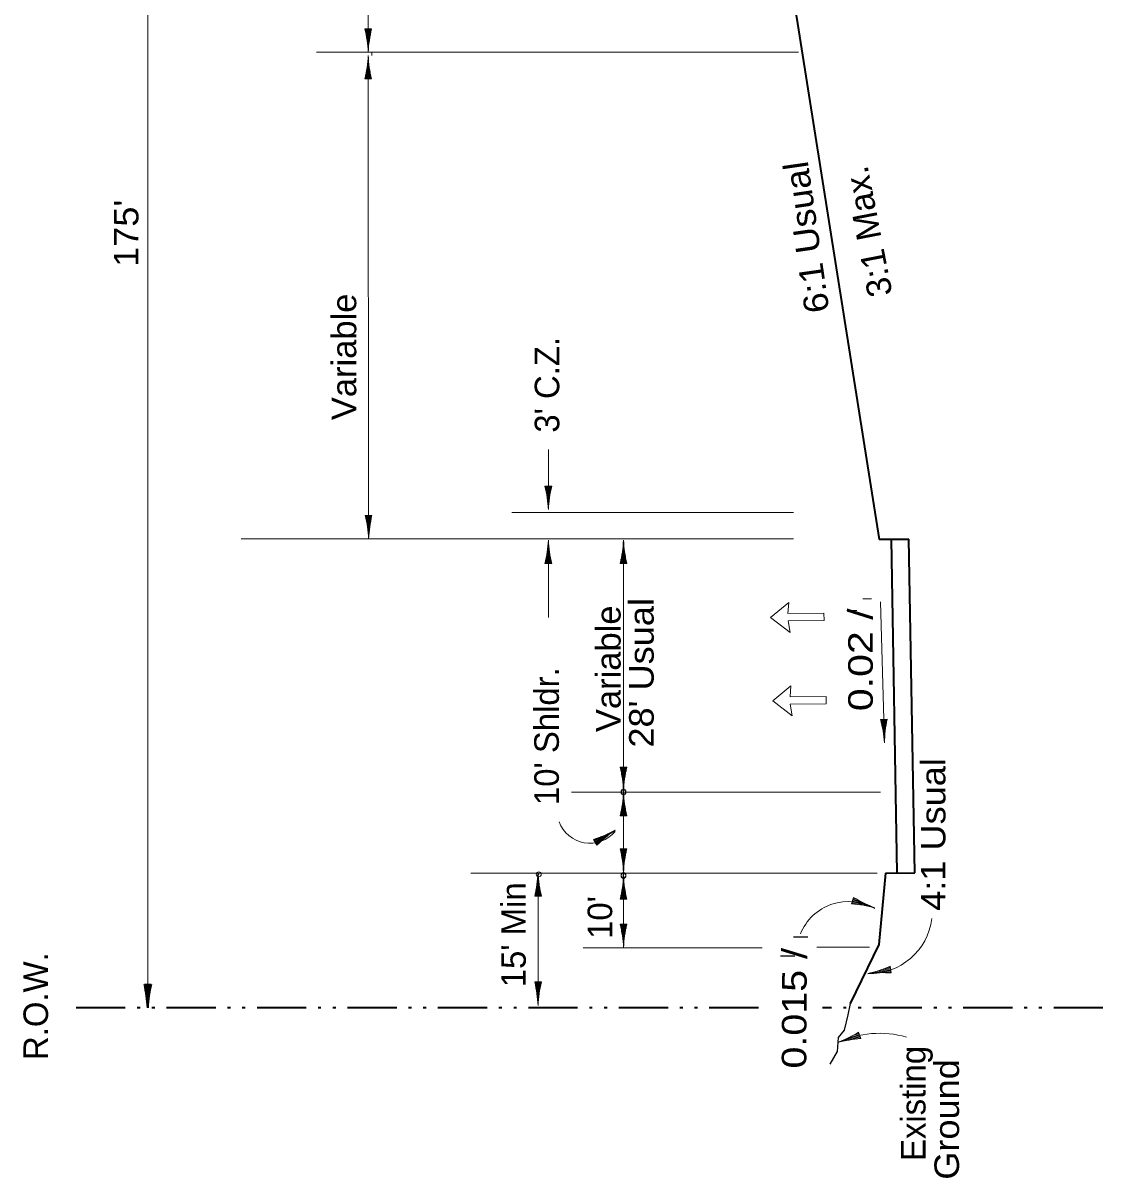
# Model space of a CAD drawing. Extents: x 2363427 to 2368559, y 6957299 to 6980140.
# Drawn here: x 2363636 to 2364251, y 6962683 to 6963341 of the extents above; entities that cross this region are included whole.
import ezdxf
from ezdxf.enums import TextEntityAlignment as Align

# ---------------------------------------------------------------- set-up
doc = ezdxf.new("R2010")
doc.units = 0
doc.header["$LTSCALE"] = 5.6
doc.header["$PDMODE"] = 32
doc.header["$PDSIZE"] = 2.8
doc.linetypes.add('DASH_DOUBLE_DOT', pattern=[9.2, 5, -1.2, 0.3, -1.2, 0.3, -1.2])
doc.linetypes.add('MEDIUM_DASHED', pattern=[4.5, 3, -1.5])
for name, color, linetype, lineweight in [('1', 7, 'Continuous', 13), ('3', 7, 'Continuous', 35), ('4', 7, 'Continuous', 13), ('40', 7, 'Continuous', 35), ('48', 7, 'Continuous', 25), ('6', 7, 'Continuous', 13), ('8', 7, 'Continuous', 13)]:
    doc.layers.add(name, color=color, linetype=linetype, lineweight=lineweight)

msp = doc.modelspace()

# ---------------------------------------------------------------- linework, layer by layer
at = {"layer": '1'}
msp.add_line((2363707.002, 6962780.153), (2363707.002, 6963655.227), dxfattribs=at)
at = {"layer": '1', "linetype": 'MEDIUM_DASHED', "lineweight": 25}
msp.add_lwpolyline([(2364107.062, 6962782.646), (2364105.71, 6962776.144), (2364103.682, 6962767.474), (2364100.302, 6962763.14), (2364099.626, 6962755.192), (2364095.57, 6962747.968)], dxfattribs=at)
at = {"layer": '3'}
for p, q in [((2364063.96, 6963424.356), (2364123.57, 6963047.006)), ((2364140.593, 6963047.007), (2364123.57, 6963047.006)), ((2364133.913, 6962856.972), (2364130.592, 6963047.007)), ((2364143.911, 6962857.081), (2364140.591, 6963047.094)), ((2364127.321, 6962856.943), (2364123.465, 6962816.178)), ((2364127.321, 6962856.943), (2364143.913, 6962857.015)), ((2364123.465, 6962816.179), (2364107.063, 6962782.648))]:
    msp.add_line(p, q, dxfattribs=at)
at = {"layer": '3', "lineweight": 13}
for p, q in [((2364077.609, 6963324.652), (2363803.11, 6963324.652)), ((2364074.775, 6963062.399), (2363914.323, 6963062.399)), ((2364074.775, 6963047.399), (2363760.2, 6963047.399))]:
    msp.add_line(p, q, dxfattribs=at)
at = {"layer": '3', "linetype": 'DASH_DOUBLE_DOT'}
for p, q in [((2364054.887, 6962780.227), (2363665.024, 6962780.227)), ((2364251.073, 6962780.227), (2364091.319, 6962780.227))]:
    msp.add_line(p, q, dxfattribs=at)
at = {"layer": '4'}
for p, q in [((2363977.999, 6963046.638), (2363977.999, 6962814.405)), ((2363978.063, 6963033.326), (2363978.063, 6963045.89)), ((2363978.063, 6963033.326), (2363978.063, 6963045.89)), ((2363977.563, 6963033.326), (2363977.563, 6963041.936)), ((2363977.563, 6963033.326), (2363977.563, 6963041.936)), ((2363978.563, 6963033.326), (2363978.563, 6963040.676)), ((2363978.563, 6963033.326), (2363978.563, 6963040.676)), ((2363979.913, 6963033.326), (2363976.083, 6963033.326)), ((2363979.913, 6963033.326), (2363976.083, 6963033.326)), ((2363976.563, 6963033.326), (2363976.563, 6963035.708)), ((2363976.563, 6963033.326), (2363976.563, 6963035.708)), ((2363977.063, 6963033.326), (2363977.063, 6963038.188)), ((2363977.063, 6963033.326), (2363977.063, 6963038.188)), ((2363979.063, 6963033.326), (2363979.063, 6963037.603)), ((2363979.063, 6963033.326), (2363979.063, 6963037.603)), ((2363979.563, 6963033.326), (2363979.563, 6963034.912)), ((2363979.563, 6963033.326), (2363979.563, 6963034.912)), ((2364124.385, 6963011.452), (2364126.661, 6962931.198)), ((2364128.197, 6962944.559), (2364124.369, 6962944.45)), ((2364124.849, 6962944.464), (2364124.917, 6962942.084)), ((2364125.349, 6962944.478), (2364125.487, 6962939.618)), ((2364125.849, 6962944.492), (2364126.093, 6962935.886)), ((2364126.348, 6962944.506), (2364126.705, 6962931.948)), ((2364126.848, 6962944.52), (2364127.057, 6962937.174)), ((2364127.348, 6962944.535), (2364127.469, 6962940.26)), ((2364127.847, 6962944.549), (2364127.893, 6962942.964)), ((2363976.083, 6962917.24), (2363979.913, 6962917.24)), ((2363976.083, 6962917.24), (2363979.913, 6962917.24)), ((2363976.433, 6962917.24), (2363976.433, 6962915.656)), ((2363976.433, 6962917.24), (2363976.433, 6962915.656)), ((2363976.933, 6962917.24), (2363976.933, 6962912.964)), ((2363976.933, 6962917.24), (2363976.933, 6962912.964)), ((2363977.433, 6962917.24), (2363977.433, 6962909.89)), ((2363977.433, 6962917.24), (2363977.433, 6962909.89)), ((2363977.933, 6962917.24), (2363977.933, 6962904.676)), ((2363977.933, 6962917.24), (2363977.933, 6962904.676)), ((2363978.433, 6962917.24), (2363978.433, 6962908.631)), ((2363978.433, 6962917.24), (2363978.433, 6962908.631)), ((2363978.933, 6962917.24), (2363978.933, 6962912.378)), ((2363978.933, 6962917.24), (2363978.933, 6962912.378)), ((2363979.433, 6962917.24), (2363979.433, 6962914.859)), ((2363979.433, 6962917.24), (2363979.433, 6962914.859)), ((2364124.346, 6962902.943), (2363948.478, 6962902.943)), ((2363978.063, 6962889.591), (2363978.063, 6962902.155)), ((2363978.063, 6962889.591), (2363978.063, 6962902.155)), ((2363977.063, 6962889.591), (2363977.063, 6962894.453)), ((2363977.063, 6962889.591), (2363977.063, 6962894.453)), ((2363977.563, 6962889.591), (2363977.563, 6962898.201)), ((2363977.563, 6962889.591), (2363977.563, 6962898.201)), ((2363978.563, 6962889.591), (2363978.563, 6962896.941)), ((2363978.563, 6962889.591), (2363978.563, 6962896.941)), ((2363979.913, 6962889.591), (2363976.083, 6962889.591)), ((2363979.913, 6962889.591), (2363976.083, 6962889.591)), ((2363976.563, 6962889.591), (2363976.563, 6962891.973)), ((2363976.563, 6962889.591), (2363976.563, 6962891.973)), ((2363979.063, 6962889.591), (2363979.063, 6962893.868)), ((2363979.063, 6962889.591), (2363979.063, 6962893.868)), ((2363979.563, 6962889.591), (2363979.563, 6962891.177)), ((2363979.563, 6962889.591), (2363979.563, 6962891.177)), ((2363961.901, 6962874.367), (2363972.641, 6962880.887)), ((2363962.861, 6962872.786), (2363960.873, 6962876.06)), ((2363961.123, 6962875.649), (2363963.158, 6962876.885)), ((2363961.382, 6962875.223), (2363965.538, 6962877.745)), ((2363961.641, 6962874.795), (2363969.001, 6962879.263)), ((2363962.16, 6962873.94), (2363968.443, 6962877.754)), ((2363962.419, 6962873.513), (2363966.075, 6962875.731)), ((2363962.679, 6962873.085), (2363964.034, 6962873.908)), ((2363976.083, 6962870.762), (2363979.913, 6962870.762)), ((2363976.083, 6962870.762), (2363979.913, 6962870.762)), ((2363976.433, 6962870.762), (2363976.433, 6962869.178)), ((2363976.433, 6962870.762), (2363976.433, 6962869.178)), ((2363976.933, 6962870.762), (2363976.933, 6962866.486)), ((2363976.933, 6962870.762), (2363976.933, 6962866.486)), ((2363977.433, 6962870.762), (2363977.433, 6962863.412)), ((2363977.433, 6962870.762), (2363977.433, 6962863.412)), ((2363977.933, 6962870.762), (2363977.933, 6962858.198)), ((2363977.933, 6962870.762), (2363977.933, 6962858.198)), ((2363978.433, 6962870.762), (2363978.433, 6962862.153)), ((2363978.433, 6962870.762), (2363978.433, 6962862.153)), ((2363978.933, 6962870.762), (2363978.933, 6962865.9)), ((2363978.933, 6962870.762), (2363978.933, 6962865.9)), ((2363979.433, 6962870.762), (2363979.433, 6962868.381)), ((2363979.433, 6962870.762), (2363979.433, 6962868.381)), ((2364122.417, 6962856.879), (2363891.088, 6962856.879)), ((2363929.268, 6962843.77), (2363929.268, 6962856.334)), ((2363929.268, 6962843.77), (2363929.268, 6962856.334)), ((2363929.332, 6962857.082), (2363929.332, 6962781.546)), ((2363978.063, 6962841.995), (2363978.063, 6962854.559)), ((2363978.063, 6962841.995), (2363978.063, 6962854.559)), ((2363928.268, 6962843.77), (2363928.268, 6962848.046)), ((2363928.268, 6962843.77), (2363928.268, 6962848.046)), ((2363928.768, 6962843.77), (2363928.768, 6962851.12)), ((2363928.768, 6962843.77), (2363928.768, 6962851.12)), ((2363929.768, 6962843.77), (2363929.768, 6962852.38)), ((2363929.768, 6962843.77), (2363929.768, 6962852.38)), ((2363930.268, 6962843.77), (2363930.268, 6962848.632)), ((2363930.268, 6962843.77), (2363930.268, 6962848.632)), ((2363977.563, 6962841.995), (2363977.563, 6962850.605)), ((2363977.563, 6962841.995), (2363977.563, 6962850.605)), ((2363978.563, 6962841.995), (2363978.563, 6962849.345)), ((2363978.563, 6962841.995), (2363978.563, 6962849.345)), ((2363927.418, 6962843.77), (2363931.248, 6962843.77)), ((2363927.418, 6962843.77), (2363931.248, 6962843.77)), ((2363927.768, 6962843.77), (2363927.768, 6962845.355)), ((2363927.768, 6962843.77), (2363927.768, 6962845.355)), ((2363930.768, 6962843.77), (2363930.768, 6962846.152)), ((2363930.768, 6962843.77), (2363930.768, 6962846.152)), ((2363979.913, 6962841.995), (2363976.083, 6962841.995)), ((2363979.913, 6962841.995), (2363976.083, 6962841.995)), ((2363976.563, 6962841.995), (2363976.563, 6962844.377)), ((2363976.563, 6962841.995), (2363976.563, 6962844.377)), ((2363977.063, 6962841.995), (2363977.063, 6962846.857)), ((2363977.063, 6962841.995), (2363977.063, 6962846.857)), ((2363979.063, 6962841.995), (2363979.063, 6962846.272)), ((2363979.063, 6962841.995), (2363979.063, 6962846.272)), ((2363979.563, 6962841.995), (2363979.563, 6962843.581)), ((2363979.563, 6962841.995), (2363979.563, 6962843.581)), ((2364107.942, 6962839.366), (2364109.107, 6962843.015)), ((2364108.657, 6962841.605), (2364116.859, 6962838.985)), ((2364108.809, 6962842.081), (2364113.441, 6962840.601)), ((2364108.961, 6962842.557), (2364111.23, 6962841.833)), ((2364108.049, 6962839.699), (2364109.559, 6962839.217)), ((2364108.201, 6962840.176), (2364112.275, 6962838.875)), ((2364108.353, 6962840.652), (2364115.354, 6962838.415)), ((2364108.505, 6962841.129), (2364120.473, 6962837.305)), ((2363976.104, 6962827.802), (2363979.934, 6962827.802)), ((2363976.104, 6962827.802), (2363979.934, 6962827.802)), ((2363976.454, 6962827.802), (2363976.454, 6962826.218)), ((2363976.454, 6962827.802), (2363976.454, 6962826.218)), ((2363976.954, 6962827.802), (2363976.954, 6962823.526)), ((2363976.954, 6962827.802), (2363976.954, 6962823.526)), ((2363977.454, 6962827.802), (2363977.454, 6962820.452)), ((2363977.454, 6962827.802), (2363977.454, 6962820.452)), ((2363977.954, 6962827.802), (2363977.954, 6962815.238)), ((2363977.954, 6962827.802), (2363977.954, 6962815.238)), ((2363978.454, 6962827.802), (2363978.454, 6962819.193)), ((2363978.454, 6962827.802), (2363978.454, 6962819.193)), ((2363978.954, 6962827.802), (2363978.954, 6962822.94)), ((2363978.954, 6962827.802), (2363978.954, 6962822.94)), ((2363979.454, 6962827.802), (2363979.454, 6962825.421)), ((2363979.454, 6962827.802), (2363979.454, 6962825.421)), ((2364056.938, 6962814.406), (2363955.062, 6962814.406)), ((2364118.17, 6962814.795), (2364088.095, 6962814.795)), ((2364130.156, 6962802.353), (2364121.676, 6962800.869)), ((2364130.07, 6962802.845), (2364125.28, 6962802.007)), ((2364129.984, 6962803.337), (2364127.638, 6962802.927)), ((2364130.562, 6962800.038), (2364129.902, 6962803.81)), ((2364130.242, 6962801.859), (2364117.866, 6962799.694)), ((2364130.329, 6962801.367), (2364123.088, 6962800.1)), ((2364130.415, 6962800.875), (2364126.202, 6962800.137)), ((2364130.501, 6962800.383), (2364128.94, 6962800.109)), ((2363931.248, 6962794.858), (2363927.418, 6962794.858)), ((2363931.248, 6962794.858), (2363927.418, 6962794.858)), ((2363927.898, 6962794.858), (2363927.898, 6962792.476)), ((2363927.898, 6962794.858), (2363927.898, 6962792.476)), ((2363928.398, 6962794.858), (2363928.398, 6962789.996)), ((2363928.398, 6962794.858), (2363928.398, 6962789.996)), ((2363928.898, 6962794.858), (2363928.898, 6962786.248)), ((2363928.898, 6962794.858), (2363928.898, 6962786.248)), ((2363929.398, 6962794.858), (2363929.398, 6962782.294)), ((2363929.398, 6962794.858), (2363929.398, 6962782.294)), ((2363929.898, 6962794.858), (2363929.898, 6962787.508)), ((2363929.898, 6962794.858), (2363929.898, 6962787.508)), ((2363930.398, 6962794.858), (2363930.398, 6962790.582)), ((2363930.398, 6962794.858), (2363930.398, 6962790.582)), ((2363930.898, 6962794.858), (2363930.898, 6962793.273)), ((2363930.898, 6962794.858), (2363930.898, 6962793.273)), ((2364112.52, 6962764.514), (2364100.575, 6962760.62)), ((2364112.675, 6962764.039), (2364104.489, 6962761.371)), ((2364112.365, 6962764.989), (2364105.377, 6962762.711)), ((2364112.21, 6962765.465), (2364108.144, 6962764.139)), ((2364112.83, 6962763.563), (2364108.207, 6962762.057)), ((2364112.055, 6962765.941), (2364110.548, 6962765.449)), ((2364112.985, 6962763.088), (2364110.721, 6962762.35)), ((2364111.947, 6962766.273), (2364113.133, 6962762.631))]:
    msp.add_line(p, q, dxfattribs=at)
at = {"layer": '4', "lineweight": 25}
for p, q in [((2364082.93, 6962820.441), (2364074.77, 6962820.441)), ((2364075.613, 6962809.618), (2364067.452, 6962809.618))]:
    msp.add_line(p, q, dxfattribs=at)
at = {"layer": '4', "lineweight": 35}
for p, q in [((2363705.088, 6962793.465), (2363708.918, 6962793.465)), ((2363705.438, 6962793.465), (2363705.438, 6962791.88)), ((2363705.938, 6962793.465), (2363705.938, 6962789.188)), ((2363706.438, 6962793.465), (2363706.438, 6962786.115)), ((2363706.938, 6962793.465), (2363706.938, 6962780.901)), ((2363707.438, 6962793.465), (2363707.438, 6962784.855)), ((2363707.938, 6962793.465), (2363707.938, 6962788.603)), ((2363708.438, 6962793.465), (2363708.438, 6962791.083))]:
    msp.add_line(p, q, dxfattribs=at)
at = {"layer": '4'}
for centre, radius, start, end in [((2363905.875, 6963050.221), 72.212, 346.47039, 357.15644), ((2363905.875, 6963050.221), 72.212, 346.47039, 357.15644), ((2364050.122, 6963050.221), 72.212, 182.84356, 193.52961), ((2364050.122, 6963050.221), 72.212, 182.84356, 193.52961), ((2364054.667, 6962925.574), 72.212, 4.46769, 15.15374), ((2364198.856, 6962929.663), 72.212, 168.09453, 178.78057), ((2363905.875, 6962900.347), 72.212, 2.84356, 13.52961), ((2363905.875, 6962900.347), 72.212, 2.84356, 13.52961), ((2364050.122, 6962900.347), 72.212, 166.47039, 177.15644), ((2364050.122, 6962900.347), 72.212, 166.47039, 177.15644), ((2363905.875, 6962906.486), 72.212, 346.47039, 357.15644), ((2363905.875, 6962906.486), 72.212, 346.47039, 357.15644), ((2364050.122, 6962906.486), 72.212, 182.84356, 193.52961), ((2364050.122, 6962906.486), 72.212, 182.84356, 193.52961), ((2363958.868, 6962892.788), 18.823, 200.84978, 319.74384), ((2363938.882, 6962944.843), 72.212, 287.73061, 298.41666), ((2364013.736, 6962821.538), 72.212, 124.10378, 134.78983), ((2363905.875, 6962853.869), 72.212, 2.84356, 13.52961), ((2363905.875, 6962853.869), 72.212, 2.84356, 13.52961), ((2364050.122, 6962853.869), 72.212, 166.47039, 177.15644), ((2364050.122, 6962853.869), 72.212, 166.47039, 177.15644), ((2363857.209, 6962860.665), 72.212, 346.47039, 357.15644), ((2363857.209, 6962860.665), 72.212, 346.47039, 357.15644), ((2364001.456, 6962860.665), 72.212, 182.84356, 193.52961), ((2364001.456, 6962860.665), 72.212, 182.84356, 193.52961), ((2363905.875, 6962858.89), 72.212, 346.47039, 357.15644), ((2363905.875, 6962858.89), 72.212, 346.47039, 357.15644), ((2364050.122, 6962858.89), 72.212, 182.84356, 193.52961), ((2364050.122, 6962858.89), 72.212, 182.84356, 193.52961), ((2364146.566, 6962904.752), 72.212, 238.75343, 249.43948), ((2364106.186, 6962811.077), 29.635, 59.62074, 157.81619), ((2364102.67, 6962767.347), 72.212, 75.12659, 85.81264), ((2364117.917, 6962835.533), 36.023, 268.88537, 352.71261), ((2363905.897, 6962810.909), 72.212, 2.84356, 13.52961), ((2363905.897, 6962810.909), 72.212, 2.84356, 13.52961), ((2364050.144, 6962810.909), 72.212, 166.47039, 177.15644), ((2364050.144, 6962810.909), 72.212, 166.47039, 177.15644), ((2364101.158, 6962870.057), 72.212, 282.77005, 293.4561), ((2364126.024, 6962727.969), 72.212, 86.39688, 97.08293), ((2363857.209, 6962777.965), 72.212, 2.84356, 13.52961), ((2363857.209, 6962777.965), 72.212, 2.84356, 13.52961), ((2364001.456, 6962777.965), 72.212, 166.47039, 177.15644), ((2364001.456, 6962777.965), 72.212, 166.47039, 177.15644), ((2364123.786, 6962708.827), 56.809, 74.22951, 114.90949), ((2364074.125, 6962827.789), 72.212, 290.89929, 301.58534), ((2364118.833, 6962690.645), 72.212, 94.52612, 105.21217)]:
    msp.add_arc(centre, radius, start, end, dxfattribs=at)
at = {"layer": '4', "lineweight": 35}
for centre, start, end in [((2363634.879, 6962776.571), 2.84356, 13.52961), ((2363779.126, 6962776.571), 166.47039, 177.15644)]:
    msp.add_arc(centre, 72.212, start, end, dxfattribs=at)
at = {"layer": '4'}
for p in [(2363977.999, 6962915.725), (2363977.999, 6962903.304), (2363977.999, 6962902.903), (2363929.73, 6962856.183), (2363977.999, 6962855.708), (2363977.999, 6962855.307)]:
    msp.add_point(p, dxfattribs=at)
at = {"layer": '40', "lineweight": 13}
for p, q in [((2364071.672, 6963004.736), (2364092.177, 6963004.931)), ((2364072.857, 6962957.343), (2364093.363, 6962957.538))]:
    msp.add_line(p, q, dxfattribs=at)
for points in [[(2364071.672, 6963004.736), (2364072.205, 6963011.051), (2364061.817, 6963002.516), (2364072.917, 6962993.913), (2364071.709, 6963000.641)], [(2364071.709, 6963000.641), (2364092.215, 6963000.836), (2364092.177, 6963004.931)], [(2364072.857, 6962957.343), (2364073.39, 6962963.658), (2364063.003, 6962955.123), (2364074.103, 6962946.521), (2364072.895, 6962953.248)], [(2364072.895, 6962953.248), (2364093.4, 6962953.443), (2364093.363, 6962957.538)]]:
    msp.add_lwpolyline(points, dxfattribs=at)
at = {"layer": '48', "lineweight": 13}
for p, q in [((2364114.42, 6963013.223), (2364119.189, 6963013.223)), ((2364110.922, 6963006.579), (2364105.198, 6963006.579))]:
    msp.add_line(p, q, dxfattribs=at)
msp.add_lwpolyline([(2364133.913, 6962856.972), (2364143.911, 6962857.081), (2364140.593, 6963047.007), (2364130.592, 6963047.007)], close=True, dxfattribs=at)
at = {"layer": '6'}
for p, q in [((2363832.6, 6963324.652), (2363832.6, 6963474.652)), ((2363830.684, 6963337.963), (2363834.514, 6963337.963)), ((2363831.034, 6963337.963), (2363831.034, 6963336.379)), ((2363831.534, 6963337.963), (2363831.534, 6963333.687)), ((2363832.034, 6963337.963), (2363832.034, 6963330.613)), ((2363832.534, 6963337.963), (2363832.534, 6963325.399)), ((2363833.034, 6963337.963), (2363833.034, 6963329.354)), ((2363833.534, 6963337.963), (2363833.534, 6963333.101)), ((2363834.034, 6963337.963), (2363834.034, 6963335.582)), ((2363832.578, 6963322.691), (2363832.809, 6963047.399)), ((2363832.643, 6963309.38), (2363832.643, 6963321.944)), ((2363834.62, 6963324.712), (2363834.62, 6963322.691)), ((2363832.143, 6963309.38), (2363832.143, 6963317.989)), ((2363833.143, 6963309.38), (2363833.143, 6963316.73)), ((2363834.493, 6963309.38), (2363830.663, 6963309.38)), ((2363831.143, 6963309.38), (2363831.143, 6963311.761)), ((2363831.643, 6963309.38), (2363831.643, 6963314.242)), ((2363833.643, 6963309.38), (2363833.643, 6963313.656)), ((2363834.143, 6963309.38), (2363834.143, 6963310.965)), ((2363935.191, 6963064.04), (2363935.191, 6963098.3)), ((2363933.276, 6963077.352), (2363937.106, 6963077.352)), ((2363933.626, 6963077.352), (2363933.626, 6963075.767)), ((2363934.126, 6963077.352), (2363934.126, 6963073.075)), ((2363934.626, 6963077.352), (2363934.626, 6963070.002)), ((2363935.126, 6963077.352), (2363935.126, 6963064.788)), ((2363935.626, 6963077.352), (2363935.626, 6963068.742)), ((2363936.126, 6963077.352), (2363936.126, 6963072.49)), ((2363936.626, 6963077.352), (2363936.626, 6963074.97)), ((2363830.894, 6963060.71), (2363834.724, 6963060.71)), ((2363831.244, 6963060.71), (2363831.244, 6963059.125)), ((2363831.744, 6963060.71), (2363831.744, 6963056.434)), ((2363832.244, 6963060.71), (2363832.244, 6963053.36)), ((2363832.744, 6963060.71), (2363832.744, 6963048.146)), ((2363833.244, 6963060.71), (2363833.244, 6963052.101)), ((2363833.744, 6963060.71), (2363833.744, 6963055.848)), ((2363834.244, 6963060.71), (2363834.244, 6963058.329)), ((2363935.191, 6963046.586), (2363935.191, 6963002.569)), ((2363935.256, 6963033.274), (2363935.256, 6963045.838)), ((2363935.256, 6963033.274), (2363935.256, 6963045.838)), ((2363934.756, 6963033.274), (2363934.756, 6963041.884)), ((2363934.756, 6963033.274), (2363934.756, 6963041.884)), ((2363935.756, 6963033.274), (2363935.756, 6963040.624)), ((2363935.756, 6963033.274), (2363935.756, 6963040.624)), ((2363937.106, 6963033.274), (2363933.276, 6963033.274)), ((2363937.106, 6963033.274), (2363933.276, 6963033.274)), ((2363933.756, 6963033.274), (2363933.756, 6963035.656)), ((2363933.756, 6963033.274), (2363933.756, 6963035.656)), ((2363934.256, 6963033.274), (2363934.256, 6963038.136)), ((2363934.256, 6963033.274), (2363934.256, 6963038.136)), ((2363936.256, 6963033.274), (2363936.256, 6963037.551)), ((2363936.256, 6963033.274), (2363936.256, 6963037.551)), ((2363936.756, 6963033.274), (2363936.756, 6963034.859)), ((2363936.756, 6963033.274), (2363936.756, 6963034.859))]:
    msp.add_line(p, q, dxfattribs=at)
for centre, start, end in [((2363760.476, 6963321.07), 2.84356, 13.52961), ((2363904.723, 6963321.07), 166.47039, 177.15644), ((2363760.455, 6963326.274), 346.47039, 357.15644), ((2363904.702, 6963326.274), 182.84356, 193.52961), ((2363863.068, 6963060.458), 2.84356, 13.52961), ((2364007.315, 6963060.458), 166.47039, 177.15644), ((2363760.686, 6963043.816), 2.84356, 13.52961), ((2363904.933, 6963043.816), 166.47039, 177.15644), ((2363863.068, 6963050.168), 346.47039, 357.15644), ((2363863.068, 6963050.168), 346.47039, 357.15644), ((2364007.315, 6963050.168), 182.84356, 193.52961), ((2364007.315, 6963050.168), 182.84356, 193.52961)]:
    msp.add_arc(centre, 72.212, start, end, dxfattribs=at)
at = {"layer": '8'}
for points in [[(2364061.817, 6963002.516), (2364072.205, 6963011.051), (2364071.672, 6963004.736), (2364092.177, 6963004.931), (2364092.215, 6963000.836), (2364071.709, 6963000.641), (2364072.917, 6962993.913)], [(2364063.003, 6962955.123), (2364073.39, 6962963.658), (2364072.857, 6962957.343), (2364093.363, 6962957.538), (2364093.4, 6962953.443), (2364072.895, 6962953.248), (2364074.103, 6962946.521)]]:
    msp.add_lwpolyline(points, close=True, dxfattribs=at)

# ---------------------------------------------------------------- texts
at = {"layer": '4'}
for s, rotation, width, p in [('6:1 Usual', 98.218, 1.1, (2364089.106, 6963220.186)), ('3:1 Max.', 100.991, 1.05, (2364124.122, 6963223.72)), ("175'", 90, 1.1, (2363701.706, 6963221.457)), ('Variable', 90, 1.05, (2363825.775, 6963151.037)), ('Variable', 90, 1.05, (2363976.359, 6962973.325)), ("28' Usual", 90, 1.1, (2363995.2, 6962971.019)), ('0.02 /', 90, 1.25, (2364120.004, 6962978.45)), ('4:1 Usual', 90.006, 1.1, (2364161.372, 6962878.926)), ('0.015 /', 89.708, 1.2, (2364082.29, 6962779.871)), ('Ground', 90, 1.1, (2364169.12, 6962716.542))]:
    msp.add_text(s, height=14, rotation=rotation, dxfattribs=dict(at, width=width)).set_placement(p, align=Align.CENTER)
for s, p in [("3' C.Z.", (2363941.429, 6963135.13)), ("10' Shldr.", (2363941.185, 6962934.927)), ("15' Min", (2363922.363, 6962821.75)), ("10' ", (2363971.567, 6962834.207)), ('R.O.W.', (2363650.226, 6962781.103)), ('Existing ', (2364150.029, 6962728.263))]:
    msp.add_text(s, height=14, rotation=90, dxfattribs=at).set_placement(p, align=Align.CENTER)

doc.saveas('drawing.dxf')
